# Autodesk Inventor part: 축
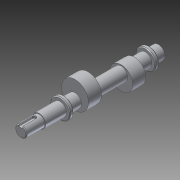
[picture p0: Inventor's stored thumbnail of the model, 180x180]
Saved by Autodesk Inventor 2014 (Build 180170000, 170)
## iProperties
Created: 2014-12
Part Number: 축
Material: 알루미늄 6061
Document SubType Name: Modeling
Designer: Owner
Mass: 170.354 g
Surface Area: 153.402 cm^2
Volume: 62.8614 cm^3
Density: 2.71 g/cm^3
Appearance: 알루미늄 - 평지
Author: Owner
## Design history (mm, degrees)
sketch "스케치1"
  geometry: L1 (-90, 0)-(90, 0); L2 (-90, 0)-(-90, 7.5); L3 (-90, 7.5)-(-66, 7.5); L4 (-66, 7.5)-(-66, 8.5); L5 (-66, 8.5)-(-39, 8.5); L6 (-39, 8.5)-(-39, 13); L7 (-39, 13)-(-34, 13); L8 (-34, 13)-(-34, 8.5); L9 (-34, 8.5)-(72, 8.5); L10 (72, 8.5)-(72, 13); L11 (72, 13)-(77, 13); L12 (77, 13)-(77, 8.5); L13 (77, 8.5)-(90, 8.5); L14 (90, 8.5)-(90, 0); 2 further points
  constraints: 28 end point, 8 parallel, 4 perpendicular, 1 coincident, 1 collinear, 1 horizontal, 1 midpoint
  dimensions: "d0" = 180 distance of L1.start L1.end; "d1" = 15 diameter of L3 L1; "d2" = 17 diameter of L5 L1; "d3" = 26 diameter of L7 L1; "d4" = 17 diameter of L9 L1; "d5" = 24 distance of L2.end L3.end; "d6" = 27 distance of L4.end L5.end; "d7" = 5 distance of L6.end L7.end; "d8" = 5 distance of L10.end L11.end; "d9" = 13 distance of L12.end L13.end; "d10" = 17 diameter of L13 L1; "d11" = 26 diameter of L11 L1
revolve "회전1" sketch "스케치1" stored, may be unused: angle "d12" = 90 deg
node "작업 평면1"
node "작업 평면2"
sketch "스케치4"
  geometry: C1 r 15 at (0, -5); 1 further point
  constraints: 1 centre point, 1 vertical alignment
  dimensions: "d21" = 30 diameter of C1; "d22" = 5 distance of point (0, 0) C1.centre
extrude "돌출2" join sketch "스케치4" distance "d23" = 17; taper "d24" = 0 deg
node "작업 평면4"
sketch "스케치5"
  geometry: C1 r 17.5 at (0, -6); 1 further point
  constraints: 1 centre point, 1 vertical alignment
  dimensions: "d28" = 35 diameter of C1; "d29" = 6 distance of point (0, 0) C1.centre
extrude "돌출3" join sketch "스케치5" distance "d30" = 17; taper "d31" = 0 deg
chamfer "모따기1" distance "d32" = 1; stored, may be unused: second distance "d33" = 2, angle "d34" = 45 deg
chamfer "모따기2" distance "d35" = 1; stored, may be unused: second distance "d36" = 2, angle "d37" = 45 deg
chamfer "모따기3" distance "d38" = 1; stored, may be unused: second distance "d39" = 2, angle "d40" = 45 deg
node "작업 평면5"
sketch "스케치6"
  geometry: L1 (0, 5.5)-(0, -12.933); L2 (-2.5, 5.5)-(-2.5, -12); L3 (2.5, -12)-(2.5, 5.5); L4 (6.5, -12)-(-6.5, -12) reference; A1 r 2.5 centre (0, 5.5) between (2.5, 5.5) and (-2.5, 5.5); 2 further points
  constraints: 8 end point, 2 point on circle, 2 point on line, 2 tangent, 1 centre point, 1 midpoint, 1 parallel, 1 vertical, 1 vertical alignment
  dimensions: "d41" = 20 dimension on A1 L4; "d42" = 5 distance between parallel lines of L2 L3; "d44" = 17.5 distance of L3.start L3.end
extrude "돌출4" cut sketch "스케치6" distance "d45" = 3; taper "d46" = 0 deg
node "솔리드1"
other parameters: "d13" = 14.5, "d18" = 14.5, "d25" = 14.5
